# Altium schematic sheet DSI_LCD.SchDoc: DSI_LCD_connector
size A4; Date: 29-OCT-2015; Author: A.B; CompanyName: STMicroelectronics; Organization: MCD/TOOLS/GNB; Address1: 12, Rue Jules HOROWITZ; Address2: 38019 Grenoble; Address3: FRANCE; DocumentNumber: MB1272; Revision: A-01; SheetNumber: 8; SheetTotal: 15; Project: STM32MP15-DISCO PI
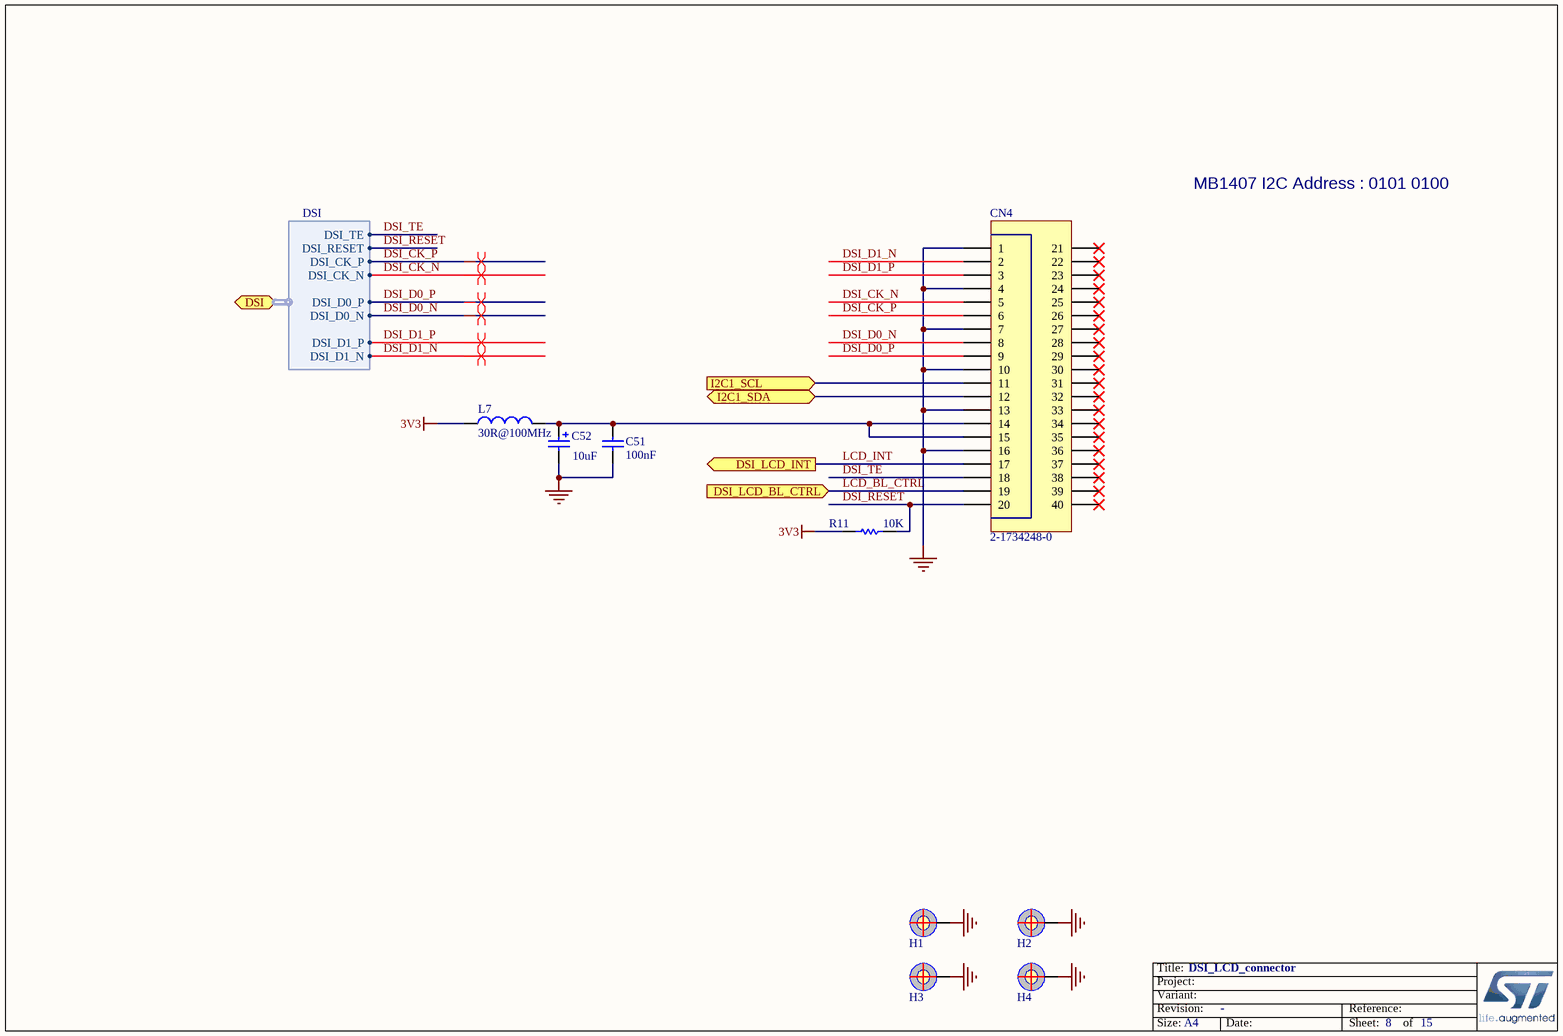
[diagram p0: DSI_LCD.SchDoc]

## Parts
C51  value 100nF  [C0402]
C52  value 10uF  [CPOL_TAJ-A_1206_H180]
CN4  value 2-1734248-0  [CON_TE-CONNECTIVITY_2-1734248-0]
H1  (no value)  [PTH_M1261-3005-N_3P5X6_M3_H14]  (no BOM)
H2  (no value)  [PTH_M1261-3005-N_3P5X6_M3_H14]  (no BOM)
H3  (no value)  [PTH_M1261-3005-N_3P5X6_M3_H14]  (no BOM)
H4  (no value)  [PTH_M1261-3005-N_3P5X6_M3_H14]  (no BOM)
L7  value 30R@100MHz  [L0603]  (hidden comment: BEAD)
R11  value 10K  [R0402]

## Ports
DSI (harness DSI), DSI_LCD_BL_CTRL (in), DSI_LCD_INT (out), I2C1_SCL (in), I2C1_SDA (bidir)

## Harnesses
DSI: DSI_CK_P, DSI_CK_N, DSI_D0_P, DSI_D0_N, DSI_D1_P, DSI_D1_N, DSI_TE, DSI_RESET

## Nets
3V3: L7.1 R11.1
GND: C51.1 C52.2 CN4.1 CN4.4 CN4.7 CN4.10 CN4.13 CN4.16 H1.1 H2.1 H3.1 H4.1
DSI_CK_N: CN4.5 ; port DSI.DSI_CK_N
DSI_CK_P: CN4.6 ; port DSI.DSI_CK_P
DSI_D0_N: CN4.8 ; port DSI.DSI_D0_N
DSI_D0_P: CN4.9 ; port DSI.DSI_D0_P
DSI_D1_N: CN4.2 ; port DSI.DSI_D1_N
DSI_D1_P: CN4.3 ; port DSI.DSI_D1_P
DSI_RESET: CN4.20 R11.2 ; port DSI.DSI_RESET
DSI_TE: CN4.18 ; port DSI.DSI_TE
I2C1_SCL: CN4.11 ; port I2C1_SCL
I2C1_SDA: CN4.12 ; port I2C1_SDA
LCD_BL_CTRL: CN4.19 ; port DSI_LCD_BL_CTRL
LCD_INT: CN4.17 ; port DSI_LCD_INT
NetC51_2: C51.2 C52.1 CN4.14 CN4.15 L7.2

Not connected (* = marked no-connect by the designer): CN4 21* 22* 23* 24* 25* 26* 27* 28* 29* 30* 31* 32* 33* 34* 35* 36* 37* 38* 39* 40*

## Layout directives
differential pair: DSI_CK_N, DSI_CK_P, DSI_D0_N, DSI_D0_P, DSI_D1_N, DSI_D1_P

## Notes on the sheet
- MB1407 I2C Address : 0101 0100

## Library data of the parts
C51 = MCD-00006: Capacitor,100nF,16V,X7R,10%,0402; Manufacturer_Part_Number: CC0402KRX7R7BB104; Manufacturer: YAGEO; Alternate_Manufacturer: MURATA; Alternate_Manufacturer_Part_Number: GCM155R71C104KA55D; Provided_By: SUBCO; Initial_Board_Reference: mb1274
C52 = MCD-00199: Polarized Capacitor,10uF,16V,10%,typeA; Manufacturer_Part_Number: TAJA106K016R; Manufacturer: AVX; Provided_By: SUBCO; ECCN_US: EAR99; ECCN_EU: NEC
CN4 = MCD-01013: Socket ,TEConn,FCC/FPC, 20pins, 1.0mm,SMT, ZIF Receptacle; Part_Type: Connector; Manufacturer: TE CONNECTIVITY; Provided_By: SUBCO; Initial_Board_Reference: MB1272
H1-H4 = MCD-00035: POSITION HOLE C6D3R5; Part_Type: Mechanical; Initial_Board_Reference: mb1274
L7 = MCD-00046: SMD Chip ferrite bead, 30R@100MHz +/-30%, 5A, 10mohm DC, S (Standard) material, 0603, T=0.8mm; Part_Type: Inductor; Manufacturer_Part_Number: MPZ1608S300A; Manufacturer: TDK; Provided_By: SUBCO; Initial_Board_Reference: MB1274
R11 = MCD-00053: Resistor,10K,0402,1%,1/16W; Manufacturer_Part_Number: RC0402FR-0710KL; Manufacturer: YAGEO; Provided_By: SUBCO; Initial_Board_Reference: mb1274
